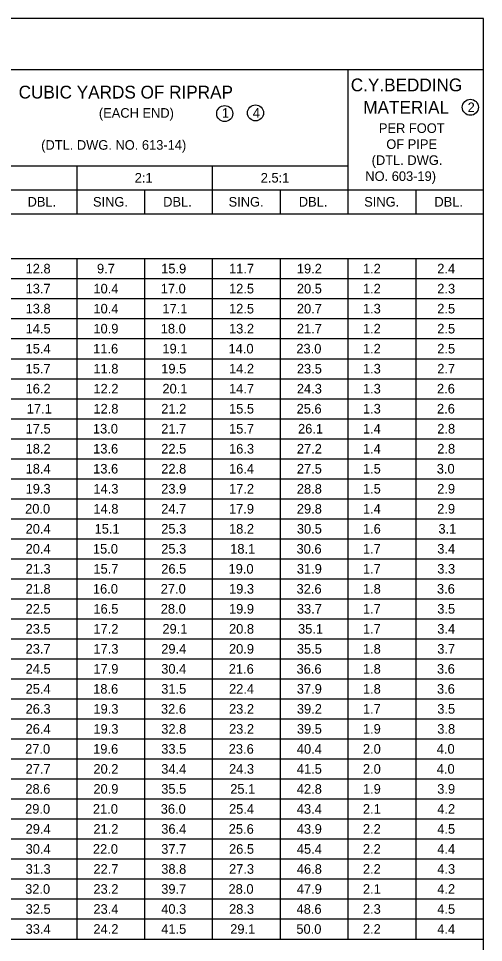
# Model space of a CAD drawing. Extents: x 49991.4 to 50047.6, y 49987.6 to 50011.4.
# Drawn here: x 50035.98 to 50038.88, y 49992.39 to 49998.16 of the extents above; entities that cross this region are included whole.
import ezdxf

# ---------------------------------------------------------------- set-up
doc = ezdxf.new("R2010")
doc.units = 0
doc.layers.add('Level 2', color=7, linetype='Continuous')

msp = doc.modelspace()

# ---------------------------------------------------------------- linework, layer by layer
at = {"layer": 'Level 2'}
for p, q in [((50038.8821, 49998.1607), (50031.0121, 49998.1607)), ((50038.8821, 49989.1307), (50038.8821, 49998.1607)), ((50038.8821, 49997.8407), (50031.0121, 49997.8407)), ((50038.0359, 49997.8407), (50038.0359, 49996.9407)), ((50032.9587, 49997.2407), (50038.0359, 49997.2407)), ((50036.3435, 49997.2407), (50036.3435, 49996.9407)), ((50037.1897, 49997.2407), (50037.1897, 49996.9407)), ((50032.1125, 49997.0907), (50038.8821, 49997.0907)), ((50036.7666, 49997.0907), (50036.7666, 49996.9407)), ((50037.6128, 49997.0907), (50037.6128, 49996.9407)), ((50038.459, 49997.0907), (50038.459, 49996.9407)), ((50031.0121, 49996.9407), (50038.8821, 49996.9407)), ((50031.0121, 49996.6607), (50038.8821, 49996.6607)), ((50036.3435, 49996.6607), (50036.3435, 49992.4107)), ((50036.7666, 49996.6607), (50036.7666, 49992.4107)), ((50037.1897, 49996.6607), (50037.1897, 49992.4107)), ((50037.6128, 49996.6607), (50037.6128, 49992.4107)), ((50038.0359, 49996.6607), (50038.0359, 49992.4107)), ((50038.459, 49996.6607), (50038.459, 49992.4107)), ((50031.0121, 49996.5357), (50038.8821, 49996.5357)), ((50031.0121, 49996.4107), (50038.8821, 49996.4107)), ((50031.0121, 49996.2857), (50038.8821, 49996.2857)), ((50031.0121, 49996.1607), (50038.8821, 49996.1607)), ((50031.0121, 49996.0357), (50038.8821, 49996.0357)), ((50031.0121, 49995.9107), (50038.8821, 49995.9107)), ((50031.0121, 49995.7857), (50038.8821, 49995.7857)), ((50031.0121, 49995.6607), (50038.8821, 49995.6607)), ((50031.0121, 49995.5357), (50038.8821, 49995.5357)), ((50031.0121, 49995.4107), (50038.8821, 49995.4107)), ((50031.0121, 49995.2857), (50038.8821, 49995.2857)), ((50031.0121, 49995.1607), (50038.8821, 49995.1607)), ((50031.0121, 49995.0357), (50038.8821, 49995.0357)), ((50031.0121, 49994.9107), (50038.8821, 49994.9107)), ((50031.0121, 49994.7857), (50038.8821, 49994.7857)), ((50031.0121, 49994.6607), (50038.8821, 49994.6607)), ((50031.0121, 49994.5357), (50038.8821, 49994.5357)), ((50031.0121, 49994.4107), (50038.8821, 49994.4107)), ((50031.0121, 49994.2857), (50038.8821, 49994.2857)), ((50031.0121, 49994.1607), (50038.8821, 49994.1607)), ((50031.0121, 49994.0357), (50038.8821, 49994.0357)), ((50031.0121, 49993.9107), (50038.8821, 49993.9107)), ((50031.0121, 49993.7857), (50038.8821, 49993.7857)), ((50031.0121, 49993.6607), (50038.8821, 49993.6607)), ((50031.0121, 49993.5357), (50038.8821, 49993.5357)), ((50031.0121, 49993.4107), (50038.8821, 49993.4107)), ((50031.0121, 49993.2857), (50038.8821, 49993.2857)), ((50031.0121, 49993.1607), (50038.8821, 49993.1607)), ((50031.0121, 49993.0357), (50038.8821, 49993.0357)), ((50031.0121, 49992.9107), (50038.8821, 49992.9107)), ((50031.0121, 49992.7857), (50038.8821, 49992.7857)), ((50031.0121, 49992.6607), (50038.8821, 49992.6607)), ((50031.0121, 49992.5357), (50038.8821, 49992.5357)), ((50031.0121, 49992.4107), (50038.8821, 49992.4107))]:
    msp.add_line(p, q, dxfattribs=at)
for centre in [(50037.4595, 49997.5707), (50038.8, 49997.6057), (50037.2673, 49997.5666)]:
    msp.add_circle(centre, 0.05, dxfattribs=at)

# ---------------------------------------------------------------- texts
for s, height, p in [('CUBIC YARDS OF RIPRAP', 0.08, (50035.9814, 49997.6607)), ('C.Y.BEDDING', 0.08, (50038.0539, 49997.7057)), ('MATERIAL ', 0.08, (50038.1321, 49997.5657)), ('2', 0.06, (50038.783, 49997.5757)), ('(EACH END)', 0.06, (50036.4821, 49997.5407)), ('1', 0.06, (50037.2498, 49997.5407)), ('4', 0.06, (50037.4425, 49997.5407)), ('PER FOOT', 0.06, (50038.2294, 49997.4457)), ('(DTL. DWG. NO. 613-14)', 0.06, (50036.1221, 49997.3407)), ('OF PIPE', 0.06, (50038.2756, 49997.3457)), ('(DTL. DWG.', 0.06, (50038.1842, 49997.2457)), ('2:1', 0.06, (50036.7059, 49997.1357)), ('2.5:1', 0.06, (50037.4921, 49997.1357)), ('NO. 603-19)', 0.06, (50038.1445, 49997.1457)), ('DBL.', 0.06, (50036.0372, 49996.9857)), ('SING.', 0.06, (50036.4453, 49996.9857)), ('DBL.', 0.06, (50036.8834, 49996.9857)), ('SING.', 0.06, (50037.2915, 49996.9857)), ('DBL.', 0.06, (50037.7296, 49996.9857)), ('SING.', 0.06, (50038.1377, 49996.9857)), ('DBL.', 0.06, (50038.5758, 49996.9857)), ('12.8', 0.06, (50036.0249, 49996.5682)), (' 9.7', 0.06, (50036.448, 49996.5682)), ('15.9', 0.06, (50036.8709, 49996.5682)), ('11.7', 0.06, (50037.2942, 49996.5682)), ('19.2', 0.06, (50037.7174, 49996.5682)), (' 1.2 ', 0.06, (50038.1075, 49996.5682)), ('2.4', 0.06, (50038.5936, 49996.5682)), ('13.7', 0.06, (50036.0249, 49996.4432)), ('10.4', 0.06, (50036.448, 49996.4432)), ('17.0', 0.06, (50036.8681, 49996.4432)), ('12.5', 0.06, (50037.2942, 49996.4432)), ('20.5', 0.06, (50037.7175, 49996.4432)), (' 1.2 ', 0.06, (50038.1075, 49996.4432)), ('2.3', 0.06, (50038.5936, 49996.4432)), ('13.8', 0.06, (50036.0249, 49996.3182)), ('10.4', 0.06, (50036.448, 49996.3182)), ('17.1', 0.06, (50036.8786, 49996.3182)), ('12.5', 0.06, (50037.2942, 49996.3182)), ('20.7', 0.06, (50037.7175, 49996.3182)), (' 1.3 ', 0.06, (50038.1075, 49996.3182)), ('2.5', 0.06, (50038.5936, 49996.3182)), ('14.5', 0.06, (50036.0249, 49996.1932)), ('10.9', 0.06, (50036.4478, 49996.1932)), ('18.0', 0.06, (50036.8682, 49996.1932)), ('13.2', 0.06, (50037.2942, 49996.1932)), ('21.7', 0.06, (50037.7175, 49996.1932)), (' 1.2 ', 0.06, (50038.1075, 49996.1932)), ('2.5', 0.06, (50038.5936, 49996.1932)), ('15.4', 0.06, (50036.0248, 49996.0682)), ('11.6', 0.06, (50036.4464, 49996.0682)), ('19.1', 0.06, (50036.8786, 49996.0682)), ('14.0', 0.06, (50037.2912, 49996.0682)), ('23.0', 0.06, (50037.7144, 49996.0682)), (' 1.2 ', 0.06, (50038.1075, 49996.0682)), ('2.5', 0.06, (50038.5936, 49996.0682)), ('15.7', 0.06, (50036.0248, 49995.9432)), ('11.8', 0.06, (50036.448, 49995.9432)), ('19.5', 0.06, (50036.8711, 49995.9432)), ('14.2', 0.06, (50037.2942, 49995.9432)), ('23.5', 0.06, (50037.7175, 49995.9432)), (' 1.3 ', 0.06, (50038.1075, 49995.9432)), ('2.7', 0.06, (50038.5936, 49995.9432)), ('16.2', 0.06, (50036.0249, 49995.8182)), ('12.2', 0.06, (50036.448, 49995.8182)), ('20.1', 0.06, (50036.8786, 49995.8182)), ('14.7', 0.06, (50037.2942, 49995.8182)), ('24.3', 0.06, (50037.7175, 49995.8182)), (' 1.3 ', 0.06, (50038.1075, 49995.8182)), ('2.6', 0.06, (50038.592, 49995.8182)), ('17.1', 0.06, (50036.0323, 49995.6932)), ('12.8', 0.06, (50036.448, 49995.6932)), ('21.2', 0.06, (50036.8712, 49995.6932)), ('15.5', 0.06, (50037.2942, 49995.6932)), ('25.6', 0.06, (50037.7159, 49995.6932)), (' 1.3 ', 0.06, (50038.1075, 49995.6932)), ('2.6', 0.06, (50038.592, 49995.6932)), ('17.5', 0.06, (50036.0249, 49995.5682)), ('13.0', 0.06, (50036.445, 49995.5682)), ('21.7', 0.06, (50036.8711, 49995.5682)), ('15.7', 0.06, (50037.2942, 49995.5682)), ('26.1', 0.06, (50037.7248, 49995.5682)), (' 1.4 ', 0.06, (50038.1075, 49995.5682)), ('2.8', 0.06, (50038.5936, 49995.5682)), ('18.2', 0.06, (50036.0249, 49995.4432)), ('13.6', 0.06, (50036.4464, 49995.4432)), ('22.5', 0.06, (50036.8711, 49995.4432)), ('16.3', 0.06, (50037.2942, 49995.4432)), ('27.2', 0.06, (50037.7174, 49995.4432)), (' 1.4 ', 0.06, (50038.1075, 49995.4432)), ('2.8', 0.06, (50038.5936, 49995.4432)), ('18.4', 0.06, (50036.0249, 49995.3182)), ('13.6', 0.06, (50036.4464, 49995.3182)), ('22.8', 0.06, (50036.8711, 49995.3182)), ('16.4', 0.06, (50037.2942, 49995.3182)), ('27.5', 0.06, (50037.7174, 49995.3182)), (' 1.5 ', 0.06, (50038.1075, 49995.3182)), ('3.0', 0.06, (50038.5906, 49995.3182)), ('19.3', 0.06, (50036.0249, 49995.1932)), ('14.3', 0.06, (50036.448, 49995.1932)), ('23.9', 0.06, (50036.8709, 49995.1932)), ('17.2', 0.06, (50037.2942, 49995.1932)), ('28.8', 0.06, (50037.7174, 49995.1932)), (' 1.5 ', 0.06, (50038.1075, 49995.1932)), ('2.9', 0.06, (50038.5934, 49995.1932)), ('20.0', 0.06, (50036.0219, 49995.0682)), ('14.8', 0.06, (50036.448, 49995.0682)), ('24.7', 0.06, (50036.8711, 49995.0682)), ('17.9', 0.06, (50037.294, 49995.0682)), ('29.8', 0.06, (50037.7174, 49995.0682)), (' 1.4 ', 0.06, (50038.1075, 49995.0682)), ('2.9', 0.06, (50038.5934, 49995.0682)), ('20.4', 0.06, (50036.0249, 49994.9432)), ('15.1', 0.06, (50036.4554, 49994.9432)), ('25.3', 0.06, (50036.8711, 49994.9432)), ('18.2', 0.06, (50037.2942, 49994.9432)), ('30.5', 0.06, (50037.7174, 49994.9432)), (' 1.6 ', 0.06, (50038.1075, 49994.9432)), ('3.1', 0.06, (50038.6009, 49994.9432)), ('20.4', 0.06, (50036.0249, 49994.8182)), ('15.0', 0.06, (50036.445, 49994.8182)), ('25.3', 0.06, (50036.8711, 49994.8182)), ('18.1', 0.06, (50037.3016, 49994.8182)), ('30.6', 0.06, (50037.7158, 49994.8182)), (' 1.7 ', 0.06, (50038.1075, 49994.8182)), ('3.4', 0.06, (50038.5936, 49994.8182)), ('21.3', 0.06, (50036.0249, 49994.6932)), ('15.7', 0.06, (50036.448, 49994.6932)), ('26.5', 0.06, (50036.8711, 49994.6932)), ('19.0', 0.06, (50037.2912, 49994.6932)), ('31.9', 0.06, (50037.7172, 49994.6932)), (' 1.7 ', 0.06, (50038.1075, 49994.6932)), ('3.3', 0.06, (50038.5936, 49994.6932)), ('21.8', 0.06, (50036.0249, 49994.5682)), ('16.0', 0.06, (50036.445, 49994.5682)), ('27.0', 0.06, (50036.8681, 49994.5682)), ('19.3', 0.06, (50037.2942, 49994.5682)), ('32.6', 0.06, (50037.7158, 49994.5682)), (' 1.8 ', 0.06, (50038.1075, 49994.5682)), ('3.6', 0.06, (50038.5919, 49994.5682)), ('22.5', 0.06, (50036.0249, 49994.4432)), ('16.5', 0.06, (50036.448, 49994.4432)), ('28.0', 0.06, (50036.8681, 49994.4432)), ('19.9', 0.06, (50037.294, 49994.4432)), ('33.7', 0.06, (50037.7174, 49994.4432)), (' 1.7 ', 0.06, (50038.1075, 49994.4432)), ('3.5', 0.06, (50038.5936, 49994.4432)), ('23.5', 0.06, (50036.0249, 49994.3182)), ('17.2', 0.06, (50036.448, 49994.3182)), ('29.1', 0.06, (50036.8785, 49994.3182)), ('20.8', 0.06, (50037.2942, 49994.3182)), ('35.1', 0.06, (50037.7248, 49994.3182)), (' 1.7 ', 0.06, (50038.1075, 49994.3182)), ('3.4', 0.06, (50038.5936, 49994.3182)), ('23.7', 0.06, (50036.0249, 49994.1932)), ('17.3', 0.06, (50036.448, 49994.1932)), ('29.4', 0.06, (50036.8711, 49994.1932)), ('20.9', 0.06, (50037.294, 49994.1932)), ('35.5', 0.06, (50037.7174, 49994.1932)), (' 1.8 ', 0.06, (50038.1075, 49994.1932)), ('3.7', 0.06, (50038.5936, 49994.1932)), ('24.5', 0.06, (50036.0249, 49994.0682)), ('17.9', 0.06, (50036.4478, 49994.0682)), ('30.4', 0.06, (50036.8711, 49994.0682)), ('21.6', 0.06, (50037.2926, 49994.0682)), ('36.6', 0.06, (50037.7158, 49994.0682)), (' 1.8 ', 0.06, (50038.1075, 49994.0682)), ('3.6', 0.06, (50038.5919, 49994.0682)), ('25.4', 0.06, (50036.0249, 49993.9432)), ('18.6', 0.06, (50036.4464, 49993.9432)), ('31.5', 0.06, (50036.8711, 49993.9432)), ('22.4', 0.06, (50037.2942, 49993.9432)), ('37.9', 0.06, (50037.7172, 49993.9432)), (' 1.8 ', 0.06, (50038.1075, 49993.9432)), ('3.6', 0.06, (50038.5919, 49993.9432)), ('26.3', 0.06, (50036.0249, 49993.8182)), ('19.3', 0.06, (50036.448, 49993.8182)), ('32.6', 0.06, (50036.8695, 49993.8182)), ('23.2', 0.06, (50037.2942, 49993.8182)), ('39.2', 0.06, (50037.7174, 49993.8182)), (' 1.7 ', 0.06, (50038.1075, 49993.8182)), ('3.5', 0.06, (50038.5936, 49993.8182)), ('26.4', 0.06, (50036.0249, 49993.6932)), ('19.3', 0.06, (50036.448, 49993.6932)), ('32.8', 0.06, (50036.8711, 49993.6932)), ('23.2', 0.06, (50037.2942, 49993.6932)), ('39.5', 0.06, (50037.7174, 49993.6932)), (' 1.9 ', 0.06, (50038.1075, 49993.6932)), ('3.8', 0.06, (50038.5936, 49993.6932)), ('27.0', 0.06, (50036.0219, 49993.5682)), ('19.6', 0.06, (50036.4464, 49993.5682)), ('33.5', 0.06, (50036.8711, 49993.5682)), ('23.6', 0.06, (50037.2926, 49993.5682)), ('40.4', 0.06, (50037.7174, 49993.5682)), (' 2.0 ', 0.06, (50038.1075, 49993.5682)), ('4.0', 0.06, (50038.5906, 49993.5682)), ('27.7', 0.06, (50036.0249, 49993.4432)), ('20.2', 0.06, (50036.448, 49993.4432)), ('34.4', 0.06, (50036.8711, 49993.4432)), ('24.3', 0.06, (50037.2942, 49993.4432)), ('41.5', 0.06, (50037.7174, 49993.4432)), (' 2.0 ', 0.06, (50038.1075, 49993.4432)), ('4.0', 0.06, (50038.5906, 49993.4432)), ('28.6', 0.06, (50036.0233, 49993.3182)), ('20.9', 0.06, (50036.4478, 49993.3182)), ('35.5', 0.06, (50036.8711, 49993.3182)), ('25.1', 0.06, (50037.3016, 49993.3182)), ('42.8', 0.06, (50037.7174, 49993.3182)), (' 1.9 ', 0.06, (50038.1075, 49993.3182)), ('3.9', 0.06, (50038.5934, 49993.3182)), ('29.0', 0.06, (50036.0219, 49993.1932)), ('21.0', 0.06, (50036.445, 49993.1932)), ('36.0', 0.06, (50036.8681, 49993.1932)), ('25.4', 0.06, (50037.2942, 49993.1932)), ('43.4', 0.06, (50037.7174, 49993.1932)), (' 2.1 ', 0.06, (50038.1075, 49993.1932)), ('4.2', 0.06, (50038.5936, 49993.1932)), ('29.4', 0.06, (50036.0249, 49993.0682)), ('21.2', 0.06, (50036.448, 49993.0682)), ('36.4', 0.06, (50036.8711, 49993.0682)), ('25.6', 0.06, (50037.2926, 49993.0682)), ('43.9', 0.06, (50037.7172, 49993.0682)), (' 2.2 ', 0.06, (50038.1075, 49993.0682)), ('4.5', 0.06, (50038.5936, 49993.0682)), ('30.4', 0.06, (50036.0249, 49992.9432)), ('22.0', 0.06, (50036.445, 49992.9432)), ('37.7', 0.06, (50036.8711, 49992.9432)), ('26.5', 0.06, (50037.2942, 49992.9432)), ('45.4', 0.06, (50037.7174, 49992.9432)), (' 2.2 ', 0.06, (50038.1075, 49992.9432)), ('4.4', 0.06, (50038.5936, 49992.9432)), ('31.3', 0.06, (50036.0249, 49992.8182)), ('22.7', 0.06, (50036.448, 49992.8182)), ('38.8', 0.06, (50036.8711, 49992.8182)), ('27.3', 0.06, (50037.2942, 49992.8182)), ('46.8', 0.06, (50037.7174, 49992.8182)), (' 2.2 ', 0.06, (50038.1075, 49992.8182)), ('4.3', 0.06, (50038.5936, 49992.8182)), ('32.0', 0.06, (50036.0219, 49992.6932)), ('23.2', 0.06, (50036.448, 49992.6932)), ('39.7', 0.06, (50036.8711, 49992.6932)), ('28.0', 0.06, (50037.2912, 49992.6932)), ('47.9', 0.06, (50037.7172, 49992.6932)), (' 2.1 ', 0.06, (50038.1075, 49992.6932)), ('4.2', 0.06, (50038.5936, 49992.6932)), ('32.5', 0.06, (50036.0249, 49992.5682)), ('23.4', 0.06, (50036.448, 49992.5682)), ('40.3', 0.06, (50036.8711, 49992.5682)), ('28.3', 0.06, (50037.2942, 49992.5682)), ('48.6', 0.06, (50037.7158, 49992.5682)), (' 2.3 ', 0.06, (50038.1075, 49992.5682)), ('4.5', 0.06, (50038.5936, 49992.5682)), ('33.4', 0.06, (50036.0249, 49992.4432)), ('24.2', 0.06, (50036.448, 49992.4432)), ('41.5', 0.06, (50036.8711, 49992.4432)), ('29.1', 0.06, (50037.3016, 49992.4432)), ('50.0', 0.06, (50037.7144, 49992.4432)), (' 2.2 ', 0.06, (50038.1075, 49992.4432)), ('4.4', 0.06, (50038.5936, 49992.4432))]:
    msp.add_text(s, height=height, dxfattribs=at).set_placement(p)

doc.saveas('drawing.dxf')
